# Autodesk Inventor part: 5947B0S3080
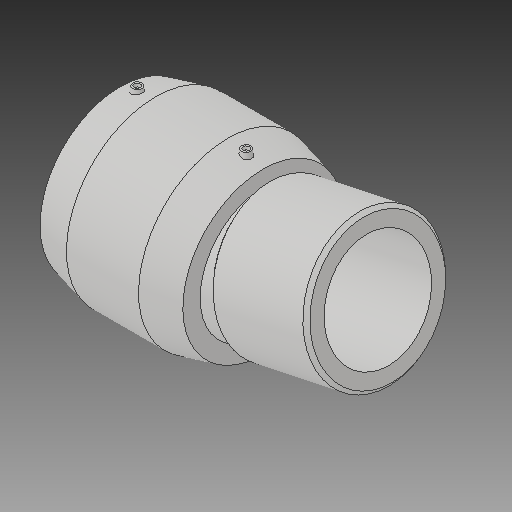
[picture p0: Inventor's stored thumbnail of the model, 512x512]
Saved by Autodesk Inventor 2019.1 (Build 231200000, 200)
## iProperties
Created: 2017-06
Part Number: 5947B0S3080
Material: Generic
Description: PLASSON ADJUSTABLE ELBOW (ONE SIDE) ASTM 8'' IPS
Document SubType Name: Modeling
Designer: KIM
Mass: 10909.3 g
Surface Area: 8060.11 cm^2
Volume: 10909.3 cm^3
Density: 1 g/cm^3
Appearance: Default
Author: KIM
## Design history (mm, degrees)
derived "5947BOS.ipt"
feature "Solid1::5947BOS.ipt"
tag "TaggingFeature1"
body "Solid1"
other parameters: "d0" = 223.09455, "d2" = 278.892, "d3" = 110.49, "d4" = 55.245, "d5" = 251.0028, "d7" = 218.7, "d8" = 168 deg, "d10" = 44.196, "d11" = 14.732, "d29" = 139.954, "d30" = 15, "d31" = 84.9884, "d34" = 5 deg, "d41" = 4, "d42" = 14, "d43" = 0, "d48" = 196.83, "d55" = 67.56273, "d57" = 168 deg, "d62" = 3, "d63" = 0, "d65" = 424.942, "d66" = 218.7, "d67" = 196.83, "d68" = 135 deg, "d69" = 148.844, "d71" = 5.57784, "d74" = 98.415, "d_" = 218.7, "L_" = 424.942, "L_1" = 110.49, "D_" = 278.892, "A_" = 139.954, "L_0" = 148, "D_1" = 218.7, "L_2" = 148.844, "d54" = 112.60455
